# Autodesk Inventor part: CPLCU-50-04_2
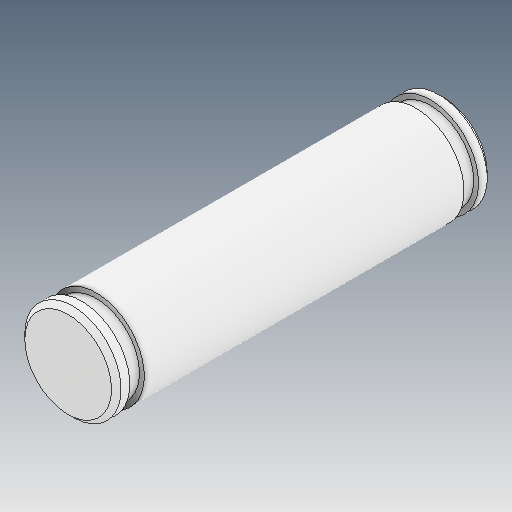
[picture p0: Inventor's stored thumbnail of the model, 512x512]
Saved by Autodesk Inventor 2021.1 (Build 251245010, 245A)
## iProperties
Created: 2021-06
Part Number: CPLCU-50-04_2
Material: Ogólny
Document SubType Name: Modeling
Designer: user
Density: 1 g/cm^3
Appearance: Domyślna
Author: user
Revision Number: ÈÎºÎ
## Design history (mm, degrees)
feature "ÊäÈë1"
node "Bryła1"
